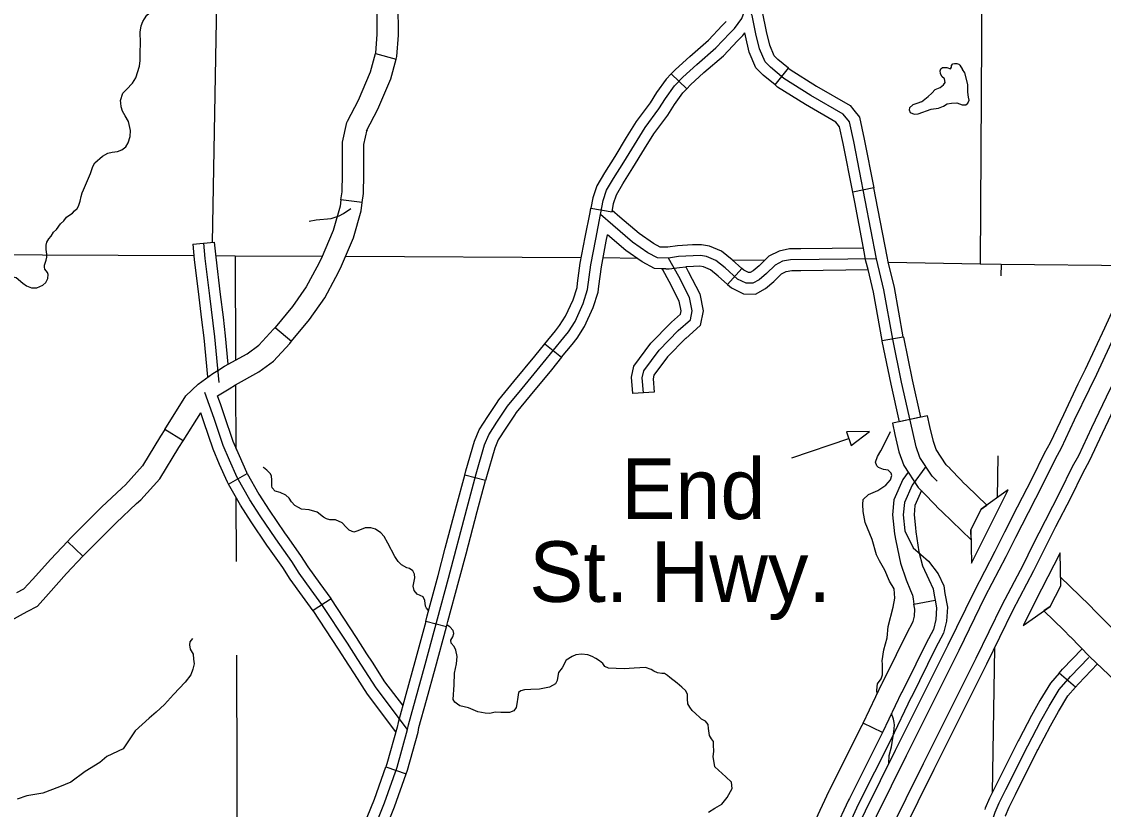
# Model space of a CAD drawing. Extents: x 813775 to 1157140, y 1757555 to 1979907.
# Drawn here: x 951173 to 966252, y 1804482 to 1815466 of the extents above; entities that cross this region are included whole.
import ezdxf

# ---------------------------------------------------------------- set-up
doc = ezdxf.new("R2010")
doc.units = 0
for name, color, linetype in [('Level 10', 7, 'Continuous'), ('Level 19', 7, 'Continuous'), ('Level 31', 7, 'Continuous'), ('Level 32', 7, 'Continuous'), ('Level 35', 7, 'Continuous'), ('Level 4', 7, 'Continuous'), ('Level 41', 7, 'Continuous'), ('Level 42', 7, 'Continuous'), ('Level 45', 7, 'Continuous'), ('Level 5', 7, 'Continuous')]:
    doc.layers.add(name, color=color, linetype=linetype)

msp = doc.modelspace()

# ---------------------------------------------------------------- linework, layer by layer
at = {"layer": 'Level 10'}
msp.add_line((964116, 1809231), (964115, 1809233), dxfattribs=at)
for points in [[(964115, 1809233), (964062, 1809287), (963921, 1809501), (963882, 1809610), (963833, 1809821), (963800, 1809970), (963311, 1809868)], [(963311, 1809868), (963346, 1809711), (963401, 1809468), (963472, 1809276), (963670, 1808972), (963757, 1808883)], [(964264, 1809077), (964116, 1809231)], [(964351, 1808991), (964302, 1809037), (964264, 1809077)], [(964407, 1808242), (964405, 1808378), (964551, 1808670), (964627, 1808724), (964351, 1808991)], [(963756, 1808885), (963903, 1808731)], [(963903, 1808731), (963948, 1808684), (964004, 1808631)], [(964004, 1808631), (964407, 1808242)], [(965656, 1807722), (965656, 1807601), (965512, 1807311), (965423, 1807249), (965700, 1806981), (965790, 1806888)], [(966149, 1807236), (966053, 1807335), (965655, 1807720)], [(966942, 1806463), (966410, 1806971), (966147, 1807238)], [(965792, 1806887), (966060, 1806615), (966596, 1806102)]]:
    msp.add_lwpolyline(points, dxfattribs=at)
at = {"layer": 'Level 19'}
for p, q in [((964474, 1806587), (963741, 1805119)), ((963893, 1805044), (964627, 1806512)), ((963741, 1805119), (962694, 1803001)), ((962847, 1802925), (963893, 1805044))]:
    msp.add_line(p, q, dxfattribs=at)
for points in [[(966005, 1810621), (966273, 1811197), (966474, 1811634)], [(966160, 1810550), (966426, 1811123), (966626, 1811559)], [(965515, 1809596), (965699, 1809986), (965903, 1810414), (966005, 1810621)], [(965669, 1809523), (965852, 1809913), (966057, 1810341), (966160, 1810550)], [(966395, 1810440), (966292, 1810231), (966087, 1809802), (965904, 1809413)], [(966058, 1809340), (966241, 1809729), (966446, 1810159), (966549, 1810368)], [(964746, 1808082), (964880, 1808352), (965057, 1808700), (965261, 1809097), (965433, 1809447), (965515, 1809596)], [(964899, 1808006), (965032, 1808276), (965208, 1808623), (965413, 1809021), (965585, 1809372), (965669, 1809523)], [(965904, 1809413), (965818, 1809256), (965645, 1808904), (965440, 1808504), (965265, 1808159), (965132, 1807891)], [(965284, 1807815), (965417, 1808083), (965591, 1808427), (965797, 1808828), (965971, 1809181), (966058, 1809340)], [(964088, 1806776), (964454, 1807525), (964746, 1808082)], [(964241, 1806701), (964606, 1807448), (964899, 1808006)], [(965132, 1807891), (964838, 1807331), (964474, 1806587)], [(964627, 1806512), (964990, 1807254), (965284, 1807815)], [(963355, 1805309), (964088, 1806776)], [(963508, 1805234), (964241, 1806701)], [(962310, 1803193), (963355, 1805309)], [(962462, 1803117), (963508, 1805234)]]:
    msp.add_lwpolyline(points, dxfattribs=at)
at = {"layer": 'Level 31'}
for p, q in [((956105, 1815023), (956395, 1814944)), ((961675, 1814583), (961865, 1814815)), ((960444, 1814531), (960226, 1814737)), ((962543, 1814039), (962543, 1814039)), ((963054, 1813147), (962759, 1813088)), ((955922, 1812943), (955624, 1812980)), ((955624, 1812980), (955624, 1812980)), ((959108, 1812865), (959403, 1812812)), ((961213, 1812025), (961014, 1811801)), ((954706, 1811202), (954937, 1811010)), ((963168, 1811020), (963463, 1811073)), ((958466, 1810974), (958700, 1810786)), ((959990, 1810300), (959691, 1810279)), ((959691, 1810279), (959691, 1810279)), ((958042, 1809979), (958042, 1809979)), ((953424, 1809620), (953170, 1809779)), ((953170, 1809779), (953170, 1809779)), ((954058, 1809018), (954319, 1809165)), ((954319, 1809165), (954319, 1809165)), ((957639, 1809066), (957349, 1809143)), ((951811, 1808218), (952028, 1808011)), ((955486, 1807419), (955235, 1807254)), ((963612, 1807345), (963907, 1807400)), ((957095, 1807025), (956806, 1807103)), ((963367, 1806640), (963367, 1806640)), ((965862, 1806185), (965636, 1806382)), ((963173, 1805556), (962903, 1805686)), ((956250, 1805077), (956533, 1804978))]:
    msp.add_line(p, q, dxfattribs=at)
for points in [[(956395, 1814944), (956404, 1814978), (956425, 1815278), (956422, 1815715), (956315, 1815908), (956246, 1815999), (956152, 1816076)], [(955961, 1815845), (956028, 1815789), (956063, 1815744), (956123, 1815636), (956125, 1815287), (956107, 1815029), (956105, 1815023)], [(961865, 1814815), (961713, 1814940), (961663, 1814991), (961601, 1815136), (961555, 1815330), (961501, 1815602), (961458, 1815688), (961433, 1815713)], [(961799, 1814675), (961611, 1814829), (961536, 1814907), (961458, 1815089), (961409, 1815298), (961358, 1815553), (961335, 1815599), (961270, 1815664)], [(960226, 1814737), (960286, 1814801), (960487, 1814981), (960748, 1815208), (960939, 1815410), (960996, 1815466)], [(960444, 1814531), (960496, 1814586), (960685, 1814757), (960956, 1814991), (961153, 1815200), (961206, 1815252)], [(961206, 1815252), (961226, 1815271), (961253, 1815309)], [(961675, 1814583), (961509, 1814719), (961409, 1814823), (961315, 1815042), (961262, 1815266), (961253, 1815309)], [(955714, 1814080), (955867, 1814373), (956036, 1814767), (956105, 1815023)], [(955980, 1813942), (956138, 1814244), (956320, 1814668), (956395, 1814944)], [(961865, 1814815), (961887, 1814797), (962253, 1814566), (962722, 1814295), (962775, 1814230)], [(960226, 1814737), (960158, 1814666), (960023, 1814477), (959933, 1814334), (959738, 1814072), (959602, 1813850)], [(963936, 1809058), (963866, 1809130), (963696, 1809388), (963641, 1809539), (963590, 1809766), (963440, 1810441), (963317, 1811039), (963194, 1811727), (963090, 1812159), (962934, 1812977), (962772, 1813795), (962714, 1814068), (962623, 1814178), (962175, 1814438), (961799, 1814675)], [(959857, 1813693), (959987, 1813903), (960181, 1814164), (960273, 1814310), (960390, 1814475), (960444, 1814531)], [(962543, 1814039), (962524, 1814062), (962098, 1814310), (961711, 1814553), (961675, 1814583)], [(962775, 1814230), (962853, 1814135), (962919, 1813825), (963054, 1813147)], [(955624, 1812980), (955639, 1813093), (955645, 1813337), (955645, 1813786), (955704, 1814061), (955714, 1814080)], [(962759, 1813088), (962625, 1813765), (962575, 1814001), (962543, 1814039)], [(955922, 1812943), (955938, 1813070), (955945, 1813333), (955945, 1813754), (955989, 1813959), (955980, 1813942)], [(959602, 1813850), (959440, 1813586), (959297, 1813359), (959191, 1813178), (959134, 1813007), (959108, 1812865)], [(959403, 1812812), (959425, 1812932), (959465, 1813053), (959553, 1813203), (959695, 1813428), (959857, 1813693)], [(963254, 1812116), (963237, 1812190), (963082, 1813006), (963054, 1813147)], [(955624, 1812980), (955613, 1812891), (955517, 1812554), (955348, 1812159), (955286, 1812043)], [(962909, 1812307), (962787, 1812948), (962759, 1813088)], [(955551, 1811902), (955619, 1812030), (955800, 1812453), (955908, 1812830), (955922, 1812943)], [(958923, 1811819), (958960, 1812097), (959029, 1812462), (959097, 1812805), (959108, 1812865)], [(960157, 1812320), (960074, 1812322), (959980, 1812372), (959779, 1812512), (959510, 1812740), (959407, 1812833)], [(963090, 1812159), (961893, 1812147), (961780, 1812124), (961676, 1812072), (961556, 1811952), (961456, 1811867), (961365, 1811818), (961271, 1811819), (961154, 1811877), (960979, 1812033), (960852, 1812137), (960719, 1812192), (960638, 1812205), (960534, 1812202), (960330, 1812189), (960190, 1812169), (960035, 1812173), (959902, 1812244), (959688, 1812393), (959412, 1812627), (959244, 1812777)], [(959221, 1811779), (959256, 1812049), (959323, 1812405), (959341, 1812491)], [(960101, 1812021), (959996, 1812023), (959823, 1812116), (959596, 1812274), (959341, 1812491)], [(961213, 1812025), (961076, 1812147), (960930, 1812267), (960760, 1812337), (960648, 1812355), (960527, 1812352), (960315, 1812338), (960182, 1812320), (960157, 1812320)], [(962033, 1812298), (961878, 1812297), (961731, 1812267), (961587, 1812195), (961455, 1812063), (961371, 1811992), (961327, 1811968), (961307, 1811968), (961239, 1812002), (961213, 1812025)], [(962909, 1812307), (962033, 1812298)], [(962972, 1812008), (962943, 1812127), (962909, 1812307)], [(959840, 1810289), (959825, 1810498), (959848, 1810599), (960061, 1810887), (960327, 1811160), (960495, 1811309), (960521, 1811432), (960482, 1811621), (960333, 1811913), (960190, 1812169)], [(963463, 1811073), (963341, 1811758), (963254, 1812116)], [(955286, 1812043), (955141, 1811770), (954949, 1811494), (954706, 1811202)], [(960110, 1812005), (960101, 1812021)], [(960151, 1812020), (960101, 1812021)], [(960231, 1811275), (960359, 1811388), (960368, 1811433), (960340, 1811570), (960201, 1811842), (960110, 1812005)], [(960151, 1812020), (960199, 1812019), (960345, 1812040), (960431, 1812045)], [(960431, 1812045), (960466, 1811983), (960625, 1811671), (960675, 1811432), (960632, 1811230), (960430, 1811050)], [(961014, 1811801), (960881, 1811919), (960774, 1812007), (960678, 1812047), (960629, 1812055), (960541, 1812052), (960431, 1812045)], [(961014, 1811801), (961069, 1811752), (961235, 1811669), (961403, 1811668), (961541, 1811743), (961658, 1811841), (961765, 1811949), (961829, 1811981), (961909, 1811997), (962036, 1811998)], [(962036, 1811998), (962972, 1812008)], [(963168, 1811020), (963047, 1811696), (962972, 1812008)], [(954937, 1811010), (955188, 1811312), (955398, 1811613), (955551, 1811902)], [(958466, 1810974), (958613, 1811156), (958672, 1811228), (958755, 1811359), (958861, 1811588), (958916, 1811761), (958923, 1811819)], [(958700, 1810786), (958845, 1810966), (958915, 1811051), (959020, 1811215), (959141, 1811480), (959210, 1811696), (959221, 1811779)], [(953908, 1810603), (954003, 1810662), (954319, 1810834), (954481, 1810956), (954686, 1811177), (954706, 1811202)], [(959691, 1810279), (959674, 1810510), (959709, 1810662), (959946, 1810984), (960223, 1811268), (960231, 1811275)], [(954067, 1810348), (954155, 1810403), (954481, 1810582), (954682, 1810732), (954912, 1810979), (954937, 1811010)], [(960430, 1811050), (960430, 1811051), (960175, 1810790), (959987, 1810535), (959976, 1810487), (959990, 1810300)], [(963409, 1809888), (963294, 1810410), (963170, 1811010), (963168, 1811020)], [(963463, 1811073), (963464, 1811067), (963587, 1810473), (963703, 1809950), (963409, 1809888)], [(957791, 1810143), (957823, 1810193), (958033, 1810446), (958327, 1810802), (958466, 1810974)], [(958700, 1810786), (958560, 1810612), (958264, 1810255), (958065, 1810014), (958042, 1809979)], [(953170, 1809779), (953463, 1810249), (953632, 1810411), (953839, 1810560), (953908, 1810603)], [(956553, 1805595), (956115, 1806176), (955860, 1806571), (955716, 1806799), (955359, 1807338), (955208, 1807543), (955040, 1807777), (954938, 1807937), (954715, 1808253), (954498, 1808573), (954353, 1808799), (954177, 1809111), (954070, 1809353), (953983, 1809557), (953856, 1809933), (953728, 1810295)], [(953904, 1810247), (954067, 1810348)], [(953948, 1810125), (953904, 1810247)], [(954319, 1809165), (954312, 1809178), (954208, 1809412), (954123, 1809611), (953998, 1809982), (953948, 1810125)], [(957349, 1809143), (957365, 1809201), (957484, 1809617), (957551, 1809775), (957672, 1809961), (957791, 1810143)], [(953424, 1809620), (953669, 1810013)], [(954058, 1809018), (954043, 1809043), (953933, 1809293), (953843, 1809504), (953714, 1809884), (953669, 1810013)], [(958042, 1809979), (957924, 1809798), (957817, 1809633), (957768, 1809517), (957654, 1809121), (957639, 1809066)], [(953170, 1809779), (953111, 1809685), (952859, 1809274), (952619, 1809009), (952570, 1808963)], [(952776, 1808745), (952833, 1808799), (953100, 1809093), (953366, 1809527), (953424, 1809620)], [(954319, 1809165), (954481, 1808876), (954623, 1808656), (954839, 1808338), (954876, 1808286)], [(957079, 1808122), (957235, 1808713), (957349, 1809143)], [(957369, 1808045), (957525, 1808636), (957639, 1809066)], [(963532, 1809183), (963455, 1809080), (963332, 1808797), (963311, 1808590), (963339, 1808325), (963357, 1808225)], [(952570, 1808963), (952284, 1808694), (951860, 1808269), (951811, 1808218)], [(954630, 1808114), (954592, 1808168), (954373, 1808490), (954224, 1808722), (954058, 1809018)], [(963715, 1808926), (963626, 1808721), (963613, 1808591), (963632, 1808409), (963640, 1808352)], [(952028, 1808011), (952074, 1808059), (952493, 1808479), (952776, 1808745)], [(963640, 1808352), (963680, 1808073), (963733, 1807877), (963821, 1807688), (963881, 1807556), (963894, 1807468), (963907, 1807400)], [(951107, 1807504), (951205, 1807557), (951324, 1807686), (951578, 1807973), (951811, 1808218)], [(954876, 1808286), (955062, 1808020), (955164, 1807862), (955330, 1807631), (955482, 1807424), (955486, 1807419)], [(963357, 1808225), (963425, 1807917), (963503, 1807684), (963562, 1807533), (963591, 1807469), (963599, 1807417), (963612, 1807345)], [(951249, 1807240), (951392, 1807317), (951547, 1807486), (951799, 1807770), (952028, 1808011)], [(955236, 1807252), (955087, 1807455), (954916, 1807693), (954813, 1807853), (954630, 1808114)], [(956806, 1807103), (956826, 1807180), (956979, 1807744), (957079, 1808122)], [(957095, 1807025), (957116, 1807102), (957269, 1807667), (957369, 1808045)], [(956063, 1806533), (955987, 1806652), (955842, 1806880), (955486, 1807419)], [(963907, 1807400), (963927, 1807292), (963918, 1807131), (963882, 1806992), (963780, 1806799), (963636, 1806507)], [(950227, 1806871), (950518, 1806949), (951021, 1807117), (951249, 1807240)], [(955811, 1806371), (955734, 1806491), (955590, 1806717), (955235, 1807254)], [(963367, 1806640), (963513, 1806935), (963601, 1807101), (963620, 1807177), (963626, 1807273), (963612, 1807345)], [(956806, 1807103), (956655, 1806541), (956528, 1806085)], [(956817, 1806005), (956944, 1806462), (957095, 1807025)], [(962903, 1805686), (963170, 1806242), (963172, 1806245), (963367, 1806640)], [(965636, 1806382), (965683, 1806437), (965956, 1806720)], [(956486, 1805933), (956238, 1806262), (956063, 1806533)], [(963636, 1806507), (963441, 1806113), (963440, 1806111), (963173, 1805556)], [(964892, 1804758), (965197, 1805368), (965382, 1805718), (965495, 1805923), (965635, 1806153), (965794, 1806335), (966050, 1806601)], [(965862, 1806185), (965904, 1806234), (966170, 1806509)], [(956388, 1805564), (955992, 1806090), (955811, 1806371)], [(965636, 1806382), (965513, 1806242), (965366, 1805998), (965250, 1805790), (965072, 1805452)], [(965337, 1805312), (965514, 1805647), (965625, 1805848), (965756, 1806065), (965862, 1806185)], [(956528, 1806085), (956420, 1805694), (956407, 1805629), (956264, 1805117), (956250, 1805077)], [(956533, 1804978), (956550, 1805027), (956699, 1805560), (956712, 1805625), (956817, 1806005)], [(962903, 1805686), (962886, 1805652), (962430, 1804745), (962426, 1804736)], [(963173, 1805556), (962713, 1804633), (962698, 1804610)], [(965072, 1805452), (965064, 1805436), (964758, 1804825), (964665, 1804636), (964606, 1804498), (964601, 1804482)], [(964884, 1804385), (964886, 1804390), (964938, 1804511), (965027, 1804691), (965330, 1805299), (965337, 1805312)], [(955877, 1804097), (956091, 1804625), (956250, 1805077)], [(956235, 1804182), (956372, 1804519), (956533, 1804978)], [(962426, 1804736), (962241, 1804335), (962132, 1804141), (962066, 1804003), (961984, 1803887)], [(965281, 1801233), (965131, 1801662), (964960, 1802071), (964830, 1802400), (964743, 1802664), (964697, 1802978), (964704, 1803546), (964697, 1804053), (964691, 1804222), (964707, 1804330), (964746, 1804444), (964801, 1804574), (964892, 1804758)], [(962698, 1804610), (962508, 1804199), (962398, 1804003), (962326, 1803851), (962225, 1803708)]]:
    msp.add_lwpolyline(points, dxfattribs=at)
at = {"layer": 'Level 32'}
for points in [[(959567, 1813507), (959863, 1813988), (960057, 1814249), (960148, 1814393), (960274, 1814570), (960391, 1814694), (960586, 1814869), (960852, 1815100), (961046, 1815305), (961111, 1815369), (961212, 1815509), (961270, 1815664)], [(959244, 1812777), (959279, 1812970), (959328, 1813116), (959425, 1813281), (959567, 1813507)], [(955179, 1812682), (955281, 1812701), (955487, 1812723), (955598, 1812758), (955662, 1812790), (955760, 1812860)], [(958794, 1811139), (958887, 1811287), (959001, 1811534), (959063, 1811729), (959108, 1812073), (959176, 1812433), (959244, 1812777)], [(957626, 1809567), (957684, 1809704), (957798, 1809879), (957944, 1810103), (958148, 1810350), (958443, 1810707), (958729, 1811061), (958794, 1811139)], [(956011, 1804030), (956232, 1804572), (956407, 1805072), (956553, 1805595), (956566, 1805660), (956799, 1806501), (956971, 1807141), (957124, 1807706), (957380, 1808674), (957509, 1809161), (957626, 1809567)]]:
    msp.add_lwpolyline(points, dxfattribs=at)
at = {"layer": 'Level 35'}
for points in [[(952829, 1815169), (952826, 1815317), (952839, 1815406), (952864, 1815466), (952887, 1815507), (952917, 1815557), (952968, 1815600), (953013, 1815620), (953096, 1815681), (953157, 1815750)], [(952552, 1814366), (952584, 1814468), (952637, 1814518), (952718, 1814607), (952763, 1814682), (952816, 1814846), (952824, 1814924), (952826, 1815033), (952829, 1815169)], [(963715, 1814350), (963651, 1814323), (963597, 1814306), (963552, 1814265), (963545, 1814234), (963560, 1814199), (963613, 1814176), (963671, 1814180), (963852, 1814244), (963956, 1814261), (964022, 1814287), (964074, 1814319), (964136, 1814329), (964211, 1814334), (964284, 1814308), (964335, 1814308), (964361, 1814329), (964381, 1814372), (964370, 1814414), (964362, 1814482), (964361, 1814591), (964321, 1814754), (964290, 1814798)], [(963715, 1814350), (963810, 1814423), (963863, 1814471), (963909, 1814519), (963976, 1814549), (964022, 1814583), (964049, 1814619), (964036, 1814668), (963999, 1814702), (963981, 1814744), (963976, 1814780), (963988, 1814808), (964010, 1814827), (964032, 1814827), (964070, 1814826), (964123, 1814808)], [(964123, 1814808), (964137, 1814832), (964136, 1814856), (964156, 1814879), (964177, 1814882), (964211, 1814882), (964238, 1814874), (964250, 1814857), (964290, 1814798)], [(952037, 1813122), (952131, 1813347), (952166, 1813447), (952194, 1813498), (952302, 1813591), (952373, 1813632), (952436, 1813647), (952511, 1813654), (952572, 1813680), (952627, 1813720), (952658, 1813775), (952685, 1813864), (952690, 1813950), (952663, 1814073), (952617, 1814151), (952577, 1814217), (952559, 1814278), (952554, 1814333), (952552, 1814366)], [(951657, 1812567), (951714, 1812646), (951759, 1812688), (951800, 1812740), (951831, 1812765), (951880, 1812797), (951909, 1812827), (951946, 1812862), (951967, 1812894), (951991, 1812962), (952004, 1813027), (952016, 1813078), (952037, 1813122)], [(951533, 1811966), (951495, 1812014), (951490, 1812042), (951490, 1812072), (951500, 1812100), (951500, 1812100), (951513, 1812140), (951526, 1812181), (951526, 1812223), (951516, 1812289), (951516, 1812350), (951526, 1812390), (951551, 1812438), (951584, 1812476), (951619, 1812529), (951657, 1812567)], [(950608, 1811702), (950608, 1811784), (950631, 1811837), (950674, 1811883), (950734, 1811921), (950817, 1811948), (950878, 1811946), (950946, 1811933), (951097, 1811900), (951190, 1811820), (951241, 1811782), (951311, 1811754), (951384, 1811752), (951470, 1811792), (951508, 1811830), (951538, 1811883), (951543, 1811938), (951533, 1811966)], [(963194, 1809562), (963286, 1809753)], [(963191, 1806706), (963240, 1806875), (963254, 1807030), (963324, 1807302), (963343, 1807428), (963335, 1807558), (963273, 1807664), (963205, 1807817), (963131, 1807947), (963088, 1808029), (963028, 1808245), (962933, 1808484), (962903, 1808637), (962898, 1808735), (962906, 1808803), (962979, 1808873), (963107, 1808928), (963221, 1809004), (963286, 1809078), (963303, 1809137), (963292, 1809170), (963251, 1809211), (963186, 1809222), (963118, 1809249), (963096, 1809271), (963077, 1809325), (963102, 1809401), (963150, 1809483), (963194, 1809562)], [(954936, 1808768), (954904, 1808821), (954855, 1808864), (954777, 1808899), (954706, 1808921), (954665, 1808965), (954662, 1808995), (954662, 1809071), (954654, 1809131), (954638, 1809166), (954592, 1809210), (954545, 1809250), (954541, 1809255)], [(956769, 1807444), (956685, 1807481), (956644, 1807532), (956630, 1807592), (956641, 1807641), (956652, 1807709), (956649, 1807761), (956625, 1807807), (956579, 1807842), (956541, 1807851), (956470, 1807891), (956421, 1807940), (956377, 1808008), (956277, 1808194), (956225, 1808289), (956179, 1808340), (956108, 1808389), (956040, 1808406), (955964, 1808408), (955861, 1808365), (955804, 1808349), (955738, 1808373), (955698, 1808417), (955641, 1808477), (955548, 1808517), (955467, 1808520), (955423, 1808534), (955382, 1808555), (955293, 1808626), (955181, 1808659), (955075, 1808667), (955032, 1808689), (954983, 1808721), (954936, 1808768)], [(956846, 1807254), (956818, 1807289), (956804, 1807316), (956793, 1807393), (956769, 1807444)], [(957404, 1805899), (957280, 1805926), (957250, 1805948), (957212, 1805975), (957188, 1806016), (957201, 1806217), (957207, 1806380), (957234, 1806511), (957242, 1806614), (957226, 1806704), (957201, 1806753), (957160, 1806799), (957158, 1806840), (957185, 1806889), (957196, 1806935), (957188, 1806974), (957141, 1807025), (957103, 1807052)], [(953554, 1806864), (953519, 1806819), (953511, 1806777), (953521, 1806718), (953562, 1806645), (953569, 1806575), (953577, 1806512), (953559, 1806438), (953532, 1806358), (953453, 1806254)], [(959712, 1806450), (959571, 1806440), (959462, 1806448), (959356, 1806451), (959305, 1806473), (959275, 1806514), (959228, 1806552), (959177, 1806587), (959128, 1806614), (959065, 1806639), (958976, 1806644), (958899, 1806636), (958845, 1806614), (958764, 1806563), (958706, 1806454), (958657, 1806391), (958649, 1806337), (958638, 1806280), (958617, 1806231), (958532, 1806184), (958391, 1806157), (958269, 1806154), (958182, 1806149), (958133, 1806135), (958100, 1806111), (958092, 1806048), (958078, 1805953), (958065, 1805901), (958032, 1805855), (957975, 1805833), (957855, 1805833), (957774, 1805836), (957700, 1805820), (957635, 1805822), (957532, 1805841), (957404, 1805899)], [(963167, 1806551), (963191, 1806706)], [(963097, 1806091), (963093, 1806145), (963104, 1806232), (963153, 1806300), (963172, 1806357), (963175, 1806439), (963172, 1806507), (963167, 1806551)], [(960823, 1805289), (960818, 1805383), (960816, 1805426), (960791, 1805467), (960764, 1805511), (960748, 1805611), (960742, 1805666), (960707, 1805712), (960650, 1805742), (960628, 1805764), (960566, 1805818), (960519, 1805862), (960487, 1805905), (960460, 1805952), (960457, 1806025), (960454, 1806085), (960432, 1806134), (960375, 1806186), (960313, 1806240), (960209, 1806322), (960177, 1806349), (960136, 1806376), (960095, 1806376), (960038, 1806387), (959986, 1806409), (959948, 1806433), (959870, 1806458), (959712, 1806450)], [(953453, 1806254), (953292, 1806082), (953164, 1805946), (953048, 1805838), (952949, 1805754), (952755, 1805578), (952589, 1805325), (952362, 1805217), (952264, 1805134), (952057, 1805010), (951858, 1804859), (951702, 1804796), (951470, 1804710), (951245, 1804669), (951109, 1804624)], [(963267, 1805233), (963300, 1805356), (963330, 1805563), (963341, 1805658), (963338, 1805691), (963327, 1805742), (963299, 1805819)], [(960747, 1804443), (960837, 1804497), (960932, 1804555), (961008, 1804647), (961076, 1804775), (961068, 1804859), (960989, 1804936), (960837, 1805077), (960812, 1805219), (960823, 1805289)], [(963263, 1805123), (963267, 1805233)]]:
    msp.add_lwpolyline(points, dxfattribs=at)
at = {"layer": 'Level 4'}
for points in [[(945885, 1812258), (949348, 1812224), (953574, 1812205)], [(953876, 1812203), (954151, 1812202), (955364, 1812196)], [(955689, 1812194), (958975, 1812178)], [(959280, 1812176), (959747, 1812169)], [(961076, 1812147), (961532, 1812140)], [(963256, 1812112), (964533, 1812091), (964828, 1812086), (966689, 1812066)]]:
    msp.add_lwpolyline(points, dxfattribs=at)
at = {"layer": 'Level 41'}
msp.add_lwpolyline([(962671, 1809747), (962738, 1809554), (962994, 1809750)], close=True, dxfattribs=at)
msp.add_lwpolyline([(962698, 1809647), (961903, 1809378)], dxfattribs=at)
at = {"layer": 'Level 42'}
for p, q in [((964925, 1808936), (964549, 1808668)), ((964670, 1808426), (964925, 1808936)), ((964549, 1808668), (964404, 1808378)), ((964404, 1808378), (964414, 1807917)), ((964414, 1807917), (964670, 1808426)), ((965649, 1808061), (965391, 1807553)), ((965657, 1807599), (965649, 1808061)), ((965391, 1807553), (965132, 1807044)), ((965510, 1807310), (965657, 1807599)), ((965132, 1807044), (965510, 1807310))]:
    msp.add_line(p, q, dxfattribs=at)
at = {"layer": 'Level 45'}
msp.add_line((953560, 1812362), (953858, 1812390), dxfattribs=at)
for points in [[(953709, 1812376), (953728, 1812165), (953793, 1811642), (953861, 1811071), (953923, 1810435)], [(953858, 1812390), (953878, 1812181), (953942, 1811661), (953980, 1811345)], [(953560, 1812362), (953579, 1812149), (953644, 1811624), (953682, 1811310)], [(953682, 1811310), (953712, 1811055), (953765, 1810513)], [(953980, 1811345), (954011, 1811087), (954049, 1810691)], [(963778, 1809263), (963586, 1809004), (963479, 1808759), (963462, 1808590), (963486, 1808367), (963601, 1808128), (963814, 1807942), (963950, 1807766), (964026, 1807599), (964042, 1807494), (964078, 1807302), (964067, 1807107), (964023, 1806937), (963914, 1806730), (963576, 1806047)], [(963575, 1806045), (963290, 1805453), (962835, 1804549), (962642, 1804130), (962531, 1803933), (962456, 1803775), (962299, 1803552)]]:
    msp.add_lwpolyline(points, dxfattribs=at)
at = {"layer": 'Level 5'}
for points in [[(964571, 1822546), (964571, 1818353), (964533, 1812091)], [(953916, 1818090), (953920, 1817547), (953829, 1812387)], [(954151, 1812202), (954155, 1810745)], [(964828, 1812086), (964825, 1811920)], [(954156, 1810404), (954159, 1809504)], [(964782, 1809411), (964772, 1808827)], [(954161, 1808834), (954164, 1807936)], [(964736, 1806736), (964702, 1804711)], [(954168, 1806631), (954183, 1801402)]]:
    msp.add_lwpolyline(points, dxfattribs=at)

# ---------------------------------------------------------------- texts
at = {"layer": 'Level 41'}
for s, p in [('End', (959532, 1808530)), ('St. Hwy.', (958249, 1807375))]:
    msp.add_text(s, height=844.8, dxfattribs=at).set_placement(p)

doc.saveas('drawing.dxf')
